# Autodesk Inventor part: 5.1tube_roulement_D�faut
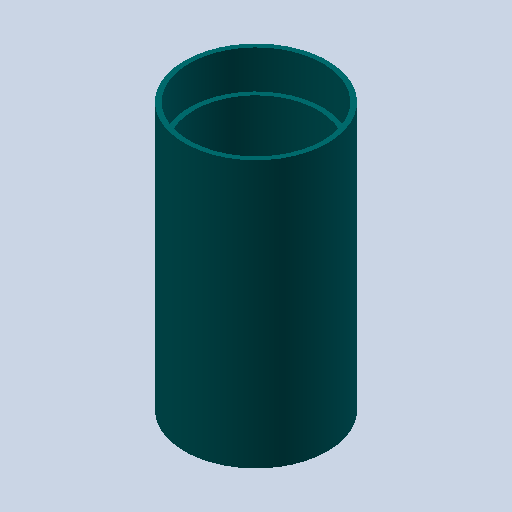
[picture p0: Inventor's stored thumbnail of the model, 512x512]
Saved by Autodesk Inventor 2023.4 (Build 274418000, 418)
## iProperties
Created: 2011-01
Part Number: 5.1tube_roulement_D�faut
Document SubType Name: Modeling
Designer: eric
Density: 1 g/cm^3
Mass: 8.49487 g
Surface Area: 103.044 cm^2
Volume: 8.49487 cm^3
Material: Générique
Appearance: 0,128,128_1
Author: eric
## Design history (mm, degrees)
feature "Base1"
node "Corps solides"
node "Corps surfaciques"
node "Solide1"
